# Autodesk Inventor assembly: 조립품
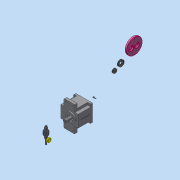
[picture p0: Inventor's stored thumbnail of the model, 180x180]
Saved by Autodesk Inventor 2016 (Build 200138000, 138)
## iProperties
Created: 2020-08
Part Number: 조립품
Material: 일반
Document SubType Name: Assembly
Designer: User
Author: User
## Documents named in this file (10)
- C:\Users\User\Desktop\700815V1007\조립품.iam
- C:\Users\User\Desktop\700815V1007\메인 축.ipt
- C:\Users\User\Desktop\700815V1007\베어링 608.ipt
- C:\Users\User\Desktop\700815V1007\베어링 6003.ipt
- C:\Users\User\Desktop\700815V1007\본체.ipt
- C:\Users\User\Desktop\700815V1007\볼트 M4.ipt
- C:\Users\User\Desktop\700815V1007\서브 축.ipt
- C:\Users\User\Desktop\700815V1007\오일 실 8 22 7.ipt
- C:\Users\User\Desktop\700815V1007\오일 실 17 32 8.ipt
- C:\Users\User\Desktop\700815V1007\커버.ipt
